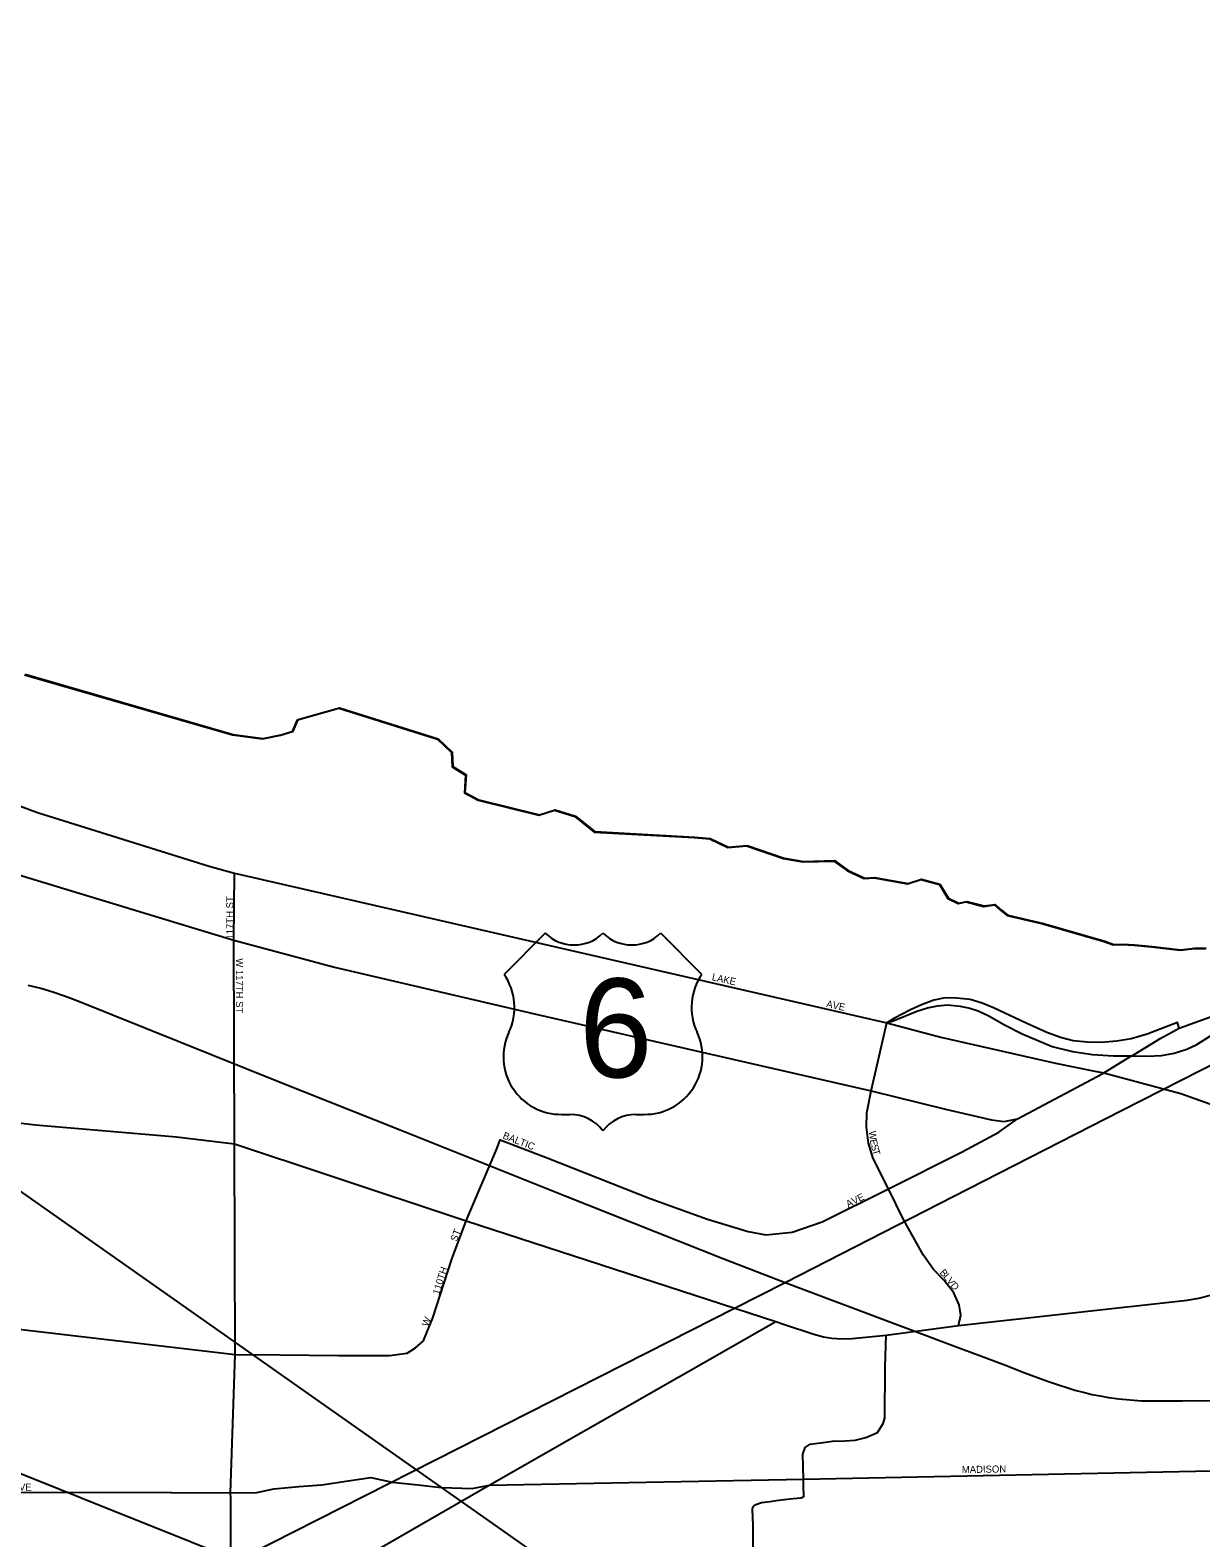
# Model space of a CAD drawing. Extents: x -561 to 1170, y 0 to 846.
# Drawn here: x 182.74 to 204.98, y 265.44 to 294.1 of the extents above; entities that cross this region are included whole.
import ezdxf

# ---------------------------------------------------------------- set-up
doc = ezdxf.new("R2010")
doc.units = 0
for name, color, linetype in [('GM_X_City_Street', 7, 'Continuous'), ('GM_X_City_Street_Text', 7, 'Continuous'), ('GM_X_County', 7, 'Continuous'), ('GM_X_Interchange_Ramps', 7, 'Continuous'), ('GM_X_Major_Lake', 7, 'Continuous'), ('GM_X_Rail_Line', 7, 'Continuous'), ('GM_X_US_Location', 7, 'Continuous'), ('GM_X_US_Route', 7, 'Continuous'), ('GM_X_US_Shield', 7, 'Continuous'), ('SH_Text', 7, 'Continuous')]:
    doc.layers.add(name, color=color, linetype=linetype)

msp = doc.modelspace()

# ---------------------------------------------------------------- linework, layer by layer
at = {"layer": 'GM_X_City_Street'}
for points in [[(181.747, 279.644), (182.872, 279.23), (186.139, 278.205), (186.62, 278.073), (186.758, 278.042)], [(186.607, 276.802), (186.607, 276.802), (186.62, 278.073)], [(186.758, 278.042), (199.009, 275.226), (200.033, 274.959), (202.212, 274.464), (202.964, 274.313)], [(186.545, 266.19), (186.544, 266.295), (186.633, 268.923), (186.617, 272.93), (186.607, 276.802)], [(198.712, 273.934), (199.009, 275.226)], [(202.964, 274.313), (203.134, 274.279), (204.598, 273.883), (210.242, 271.869)], [(200.373, 269.475), (200.414, 269.673), (200.383, 269.87), (200.284, 270.094), (200.097, 270.333), (199.894, 270.541), (199.702, 270.817), (199.327, 271.493), (199.039, 272.075), (198.75, 272.65), (198.662, 272.94), (198.624, 273.245), (198.632, 273.516), (198.712, 273.934)], [(191.647, 272.953), (191.667, 273.007), (192.56, 272.661), (194.511, 271.89), (195.605, 271.496), (196.377, 271.261), (196.711, 271.2), (197.214, 271.247), (197.782, 271.444), (199.039, 272.075), (200.443, 272.774), (201.141, 273.151), (201.492, 273.406)], [(190.212, 269.202), (190.385, 269.619), (190.747, 270.736), (191.02, 271.463), (191.6, 272.831), (191.647, 272.953)], [(163.605, 271.045), (164.323, 271.042), (164.998, 271.04), (165.684, 271.059), (166.37, 271.05), (169.41, 270.892), (170.03, 270.857), (170.673, 270.795), (171.007, 270.675), (171.191, 270.652), (171.433, 270.56), (171.568, 270.505), (171.821, 270.412), (172.086, 270.368), (172.674, 270.371), (173.247, 270.347), (173.846, 270.306), (174.413, 270.239), (177.985, 269.944), (179.088, 269.853), (179.973, 269.703), (186.633, 268.923)], [(177.681, 258.507), (178.816, 259.161), (186.553, 263.616), (191.454, 266.438), (196.9, 269.548)], [(189.459, 268.907), (189.563, 268.907), (189.895, 268.95), (190.053, 269.048), (190.205, 269.184), (190.212, 269.202)], [(196.911, 266.147), (197.059, 266.167), (197.232, 266.188), (197.383, 266.201), (197.431, 266.225), (197.431, 266.262), (197.429, 266.392), (197.428, 266.555), (197.412, 267.027), (197.459, 267.155), (197.554, 267.221), (197.799, 267.249), (197.979, 267.273), (198.215, 267.282), (198.408, 267.296), (198.612, 267.348), (198.834, 267.442), (198.94, 267.609), (198.973, 267.712), (198.978, 268.691), (199, 269.291)], [(186.633, 268.923), (187.481, 268.916)], [(187.481, 268.916), (188.591, 268.907), (189.459, 268.907)], [(191.454, 266.438), (197.428, 266.555), (205.496, 266.721), (211.806, 266.796), (215.172, 266.847)], [(187.637, 266.395), (187.637, 266.395), (187.841, 266.415), (188.279, 266.445), (188.776, 266.519), (189.208, 266.588), (189.613, 266.494), (190.045, 266.455), (190.552, 266.398), (191.135, 266.374), (191.454, 266.438)], [(180.986, 266.304), (181.091, 266.304), (185.404, 266.297)], [(185.404, 266.297), (185.426, 266.297), (186.544, 266.295), (187.041, 266.299), (187.366, 266.368), (187.637, 266.395)], [(186.554, 263.455), (186.553, 263.616), (186.545, 266.159), (186.545, 266.19)], [(196.497, 261.343), (196.484, 263.715), (196.468, 265.675), (196.459, 265.985), (196.465, 266.019), (196.478, 266.043), (196.496, 266.061), (196.523, 266.073), (196.629, 266.107), (196.797, 266.132), (196.911, 266.147)]]:
    msp.add_lwpolyline(points, dxfattribs=at)
at = {"layer": 'GM_X_County'}
msp.add_lwpolyline([(182.629, 281.847), (186.582, 280.702), (187.151, 280.625), (187.491, 280.697), (187.718, 280.764), (187.815, 280.986), (188.598, 281.213), (190.475, 280.619), (190.742, 280.366), (190.754, 280.095), (191.009, 279.934), (190.984, 279.599), (191.245, 279.459), (192.4, 279.174), (192.697, 279.274), (193.082, 279.152), (193.452, 278.856), (195.353, 278.749), (195.645, 278.724), (195.992, 278.564), (196.344, 278.593), (197.049, 278.354), (197.412, 278.291), (198.002, 278.305), (198.263, 278.118), (198.578, 277.973), (198.768, 277.985), (199.402, 277.87), (199.656, 277.953), (200.008, 277.858), (200.172, 277.594), (200.367, 277.497), (200.519, 277.531), (200.847, 277.443), (201.058, 277.471), (201.178, 277.363), (201.298, 277.267), (201.976, 277.108), (203.137, 276.773), (203.311, 276.709), (203.473, 276.72), (203.706, 276.705), (204.036, 276.675), (204.584, 276.607), (204.849, 276.641), (205.066, 276.642)], dxfattribs=at)
at = {"layer": 'GM_X_Interchange_Ramps'}
for points in [[(204.565, 275.13), (204.532, 275.232), (203.957, 275.011), (203.654, 274.923), (203.379, 274.878), (203.081, 274.856), (202.821, 274.863), (202.553, 274.889), (202.311, 274.947), (202.048, 275.047), (201.659, 275.22), (201.039, 275.515), (200.824, 275.604), (200.592, 275.673), (200.34, 275.699), (200.119, 275.704), (199.904, 275.662), (199.667, 275.573), (199.462, 275.473), (199.157, 275.315), (199.009, 275.226)], [(199.009, 275.226), (199.149, 275.272), (199.581, 275.45), (199.781, 275.517), (199.974, 275.555), (200.16, 275.569), (200.405, 275.547), (200.584, 275.51), (200.747, 275.458), (200.933, 275.369), (201.26, 275.183), (201.58, 275.019), (202.152, 274.781), (202.539, 274.685), (202.918, 274.625), (203.319, 274.603), (203.658, 274.599), (203.958, 274.595), (204.226, 274.61), (204.471, 274.655), (204.709, 274.729), (204.902, 274.818), (205.207, 275.012)]]:
    msp.add_lwpolyline(points, dxfattribs=at)
at = {"layer": 'GM_X_Major_Lake'}
for points in [[(182.64, 281.854), (186.594, 280.709), (187.162, 280.632), (187.503, 280.704), (187.73, 280.771), (187.826, 280.993), (188.61, 281.22), (190.487, 280.626), (190.753, 280.373), (190.766, 280.102), (191.021, 279.941), (190.996, 279.605), (191.257, 279.466), (192.411, 279.181), (192.709, 279.281), (193.094, 279.158), (193.463, 278.863), (195.364, 278.756), (195.657, 278.731), (196.004, 278.57), (196.356, 278.6), (197.061, 278.36), (197.424, 278.298), (198.014, 278.312), (198.275, 278.124), (198.59, 277.98), (198.779, 277.992), (199.413, 277.877), (199.667, 277.96), (200.02, 277.865), (200.184, 277.6), (200.379, 277.504), (200.531, 277.538)], [(200.531, 277.538), (200.859, 277.45), (201.07, 277.478), (201.19, 277.37), (201.31, 277.273), (201.988, 277.115), (203.149, 276.78), (203.322, 276.715), (203.485, 276.727), (203.718, 276.712), (204.048, 276.682), (204.596, 276.614), (204.861, 276.648), (205.077, 276.649)]]:
    msp.add_lwpolyline(points, dxfattribs=at)
at = {"layer": 'GM_X_Rail_Line'}
for points in [[(197.077, 270.293), (200.273, 271.928), (203.47, 273.56), (209.487, 276.62), (211.146, 277.453), (212.262, 278.028), (213.918, 278.864), (215.28, 279.559), (215.714, 279.774), (217.261, 280.569), (217.693, 280.79), (218.131, 281.017), (218.428, 281.186), (218.73, 281.358), (219.028, 281.542), (219.677, 281.985), (220.829, 282.791), (222.601, 284.04), (224.719, 285.505)], [(182.689, 275.947), (182.936, 275.886), (183.169, 275.818), (183.388, 275.745), (183.644, 275.648), (187.487, 274.103), (189.765, 273.197), (192.9, 271.943), (195.912, 270.743), (197.077, 270.293)], [(196.115, 269.804), (197.077, 270.293)], [(197.077, 270.293), (200.466, 269.016), (200.81, 268.889), (201.262, 268.719), (201.635, 268.578), (202.065, 268.418), (202.274, 268.345), (202.428, 268.294), (202.582, 268.247), (202.739, 268.207), (202.908, 268.166), (203.066, 268.135), (203.222, 268.107), (203.42, 268.08), (203.631, 268.059), (203.849, 268.045), (204.2, 268.041), (204.621, 268.042), (206.109, 268.052)], [(167.616, 243.881), (171.77, 250.74), (174.152, 254.528), (175.203, 256.193), (175.774, 257.101), (176.133, 257.69), (176.485, 258.168), (176.859, 258.623), (177.077, 258.867), (177.653, 259.482), (178.205, 260.055), (178.669, 260.471), (179.309, 260.965), (179.973, 261.476), (180.726, 261.936), (182.199, 262.745), (184.642, 263.982), (194.88, 269.177), (196.115, 269.804)]]:
    msp.add_lwpolyline(points, dxfattribs=at)
at = {"layer": 'GM_X_US_Route'}
for points in [[(146.793, 279.944), (154.72, 280.588), (158.229, 280.868), (163.988, 280.826), (165.715, 280.762), (171.059, 280.399), (171.619, 280.36), (175.976, 279.984), (176.373, 279.904), (176.91, 279.745), (186.607, 276.802)], [(186.607, 276.802), (188.515, 276.288), (192.318, 275.397), (198.712, 273.934), (200.125, 273.588), (200.996, 273.386), (201.24, 273.352), (201.335, 273.373)], [(203.103, 274.262), (203.134, 274.279), (203.658, 274.599), (203.707, 274.629), (204.217, 274.936), (204.565, 275.13), (206.031, 275.662)], [(171.266, 274.567), (171.294, 274.564), (171.379, 274.555), (172.056, 274.487), (172.738, 274.424), (173.463, 274.346), (174.194, 274.273), (174.946, 274.2), (175.498, 274.137), (176.018, 274.096), (176.678, 274.011), (177.452, 273.922), (178.145, 273.844), (178.805, 273.76), (179.52, 273.676), (180.245, 273.592), (180.889, 273.529), (181.625, 273.44), (182.188, 273.366), (182.838, 273.287), (185.516, 273.064), (186.617, 272.93)], [(201.335, 273.373), (201.492, 273.406), (203.103, 274.262)], [(186.617, 272.93), (188.409, 272.332), (191.02, 271.463), (196.9, 269.548), (197.046, 269.5)], [(200.373, 269.475), (200.373, 269.475), (204.715, 269.959), (204.935, 269.997), (205.21, 270.066), (210.242, 271.869)], [(197.046, 269.5), (197.621, 269.311), (197.809, 269.262), (197.966, 269.234), (198.156, 269.223), (198.352, 269.225), (199, 269.291), (200.373, 269.475)]]:
    msp.add_lwpolyline(points, dxfattribs=at)
at = {"layer": 'GM_X_US_Shield'}
for p, q in [((192.521, 276.933), (191.738, 276.15)), ((195.497, 276.15), (194.714, 276.933)), ((192.834, 273.488), (192.991, 273.488)), ((194.244, 273.488), (194.4, 273.488))]:
    msp.add_line(p, q, dxfattribs=at)
for centre, radius, start, end in [((193.069, 277.492), 0.783, 225.573, 314.427), ((194.165, 277.492), 0.783, 225.573, 314.427), ((190.84, 275.521), 1.096, 334.5471, 35.0009), ((196.395, 275.521), 1.096, 144.9991, 205.4529), ((192.822, 274.584), 1.096, 154.8319, 270.6383), ((194.413, 274.584), 1.096, 269.3617, 25.1681), ((192.991, 272.704), 0.783, 36.8699, 90), ((194.244, 272.704), 0.783, 90, 143.1301)]:
    msp.add_arc(centre, radius, start, end, dxfattribs=at)
at = {"layer": 'SH_Text'}
msp.add_lwpolyline([(129.942, 309.069), (200.26, 259.555), (129.942, 287.747)], close=True, dxfattribs=at)

# ---------------------------------------------------------------- texts
at = {"layer": 'GM_X_City_Street_Text'}
for s, rotation, p in [('117TH ST', 90, (186.595, 276.812)), ('W 117TH ST', 270, (186.645, 276.455)), ('LAKE', 347.4661, (195.678, 276.04)), ('AVE', 347.9042, (197.852, 275.53)), ('BALTIC', 338.6324, (191.702, 273.034)), ('W', 276.2158, (198.668, 273.167)), ('E', 280.21, (198.686, 273.003)), ('S', 285.8061, (198.706, 272.896)), ('T', 286.2775, (198.732, 272.803)), ('AVE', 26.565, (198.275, 271.714)), ('ST', 68.2011, (190.838, 271.059)), ('110TH', 72.3006, (190.504, 270.048)), ('B', 311.9078, (200.004, 270.473)), ('L', 310.4561, (200.075, 270.394)), ('V', 308.8373, (200.136, 270.322)), ('D', 308.6496, (200.21, 270.23)), ('W', 67.3711, (190.291, 269.444)), ('MADISON', 0.8809, (200.436, 266.668)), ('AVE', 0, (182.403, 266.335))]:
    msp.add_text(s, height=0.135, rotation=rotation, dxfattribs=at).set_placement(p)
at = {"layer": 'GM_X_US_Location'}
for s in ['/', '0']:
    msp.add_text(s, height=0.0027, dxfattribs=at).set_placement((193.616, 275.117))
msp.add_text('6', height=0.0027, rotation=0, dxfattribs=at).set_placement((193.344, 274.558))
at = {"layer": 'GM_X_US_Shield'}
msp.add_text('6', height=1.879, dxfattribs=at).set_placement((193.163, 274.192))

doc.saveas('drawing.dxf')
